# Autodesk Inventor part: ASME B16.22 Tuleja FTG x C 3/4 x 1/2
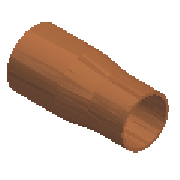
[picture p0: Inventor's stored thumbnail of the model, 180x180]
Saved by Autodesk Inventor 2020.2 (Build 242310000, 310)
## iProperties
Manager: www.cadconsulting.pl
Company: Fabian Stasiak CAD Consulting
IsCustomPart: 0
NAME: PIPING: ASME B16.22 Bushing FTG x C
DATA: <meta><inlinegroups number="1" deflen="2.54"></inlinegroups><connections number="2"></connections><angles><a>3.14159265358979</a></angles></meta>
Created: 2014-02
Part Number: ASME B16.22 Tuleja FTG x C 3/4 x 1/2
Material: Miedź kuta
Description: Tuleja
Document SubType Name: Modeling
Standard: ASME B16.22
Designer: F.Stasiak
Standard Revision: 2001
Standards Organization: ANSI
Language: pl-PL
Size Designation: 3/4 x 1/2
Categories: <MemberInstance><Categories><Category DisplayName="Rury cienko- i grubościenne" InternalName="4347fa0f-2144-441d-94cd-e3e15c92b736" Mnemonic="TUBEANDPIPE"><Cate
Density: 1 g/cm^3
Appearance: Miedź - satynowa
Catalog Web Link: www.expertbooks.pl
Author: F.Stasiak
Subject: Zbiór ćwiczeń. Autodesk Inventor 2020. Kurs Professional
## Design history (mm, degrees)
sketch "Sketch1"
  geometry: L1 (0, 0)-(-42.926, 0); L2 (0, 0)-(0, 10.236); L3 (0, 10.236)-(0, 11.074); L4 (0, 11.074)-(-20.574, 11.074); L5 (-20.574, 11.074)-(-30.226, 8.7); L6 (-30.226, 8.7)-(-42.926, 8.699); L7 (-42.926, 8.699)-(-42.926, 7.963); L8 (-42.926, 7.963)-(-30.251, 7.963); L9 (-20.574, 10.236)-(0, 10.236); L10 (-42.926, 7.963)-(-42.926, 0); L11 (-30.226, 8.7)-(-30.226, 0); L12 (-20.574, 11.074)-(-20.574, 10.236); L13 (-30.226, 7.861)-(-20.574, 10.236); L14 (-30.226, 7.861)-(-30.251, 7.963); L15 (-20.574, 10.236)-(-20.574, 0); 1 further point
  constraints: 30 end point, 6 perpendicular, 5 parallel, 3 point on line, 1 coincident, 1 collinear, 1 horizontal
  dimensions: "d0" = 0.7366 distance of L6.end L7.end (= T2); "d1" = 0.8382 distance of L2.end L3.end (= T1); "d2" = 11.0744 distance of L1.start L3.end (= 0.5 x A); "d3" = 7.9629 distance of L7.end L1.end (= 0.5 x F1); "d4" = 12.7 distance of L11.end L1.end (= G); "d5" = 20.574 horizontal distance of L9.start L1.start (= K1); "d6" = 30.226 distance of L1.start L11.end (= L); "d7" = 0.8382 distance of L13.start L5.end (= T1)
revolve "Revolve1" sketch "Sketch1" stored, may be unused: angle "d9" = 90 deg
workpoint "Work Point1"
workpoint "Work Point2"
workaxis "Work Axis1"
workpoint "Work Point3"
workaxis "Work Axis2"
workpoint "Work Point4"
body "Solid1"
other parameters: "L" = 30.226 [user parameter; used in 1 equation term], "G" = 12.7 [user parameter; used in 1 equation term], "T1" = 0.8382 [user parameter; used in 2 equation terms], "F1" = 15.9258 [user parameter; used in 1 equation term], "A" = 22.1488 [user parameter; used in 1 equation term], "T2" = 0.7366 [user parameter; used in 1 equation term], "K1" = 20.574 [user parameter; used in 1 equation term], "Size_Designation" = 12.345 [user parameter]
